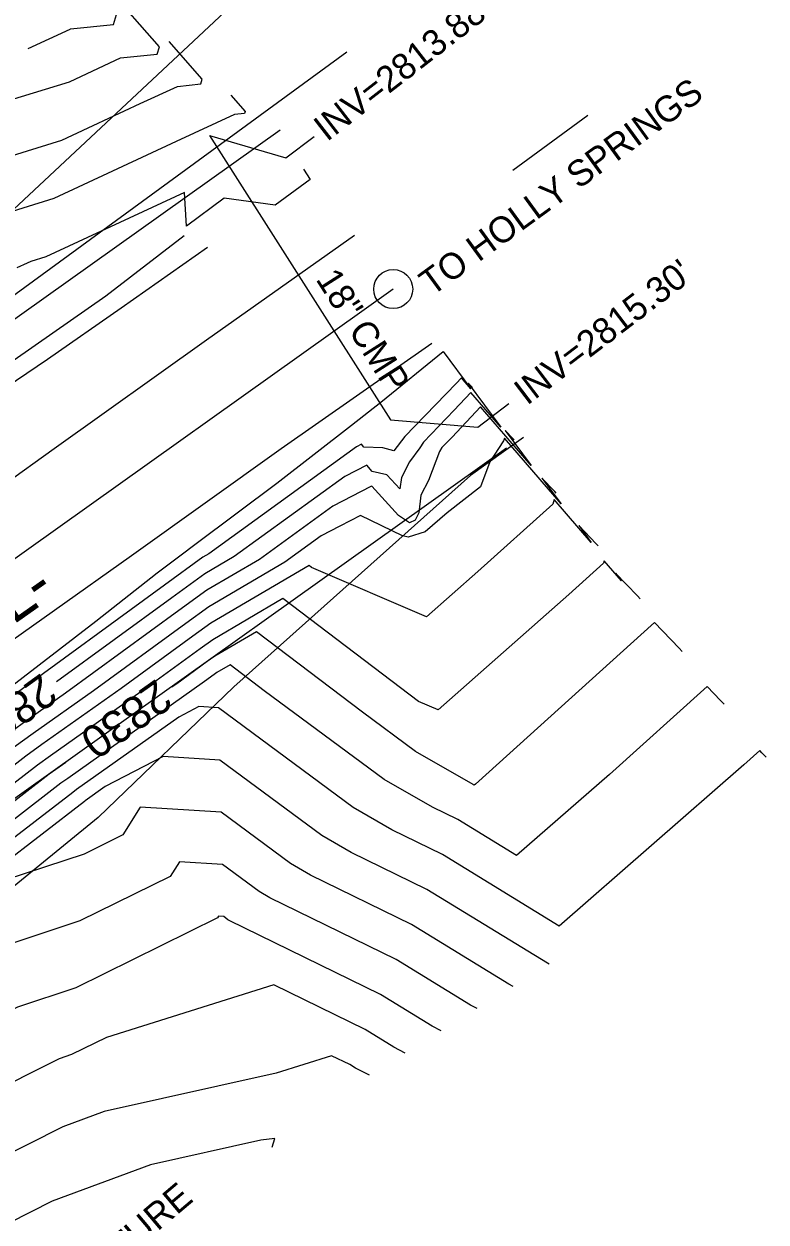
# Model space of a CAD drawing. Extents: x 1284446 to 1285480, y 969739 to 970628.
# Drawn here: x 1285132.8 to 1285246.9, y 970247.2 to 970431.3 of the extents above; entities that cross this region are included whole.
import ezdxf

# ---------------------------------------------------------------- set-up
doc = ezdxf.new("R2010")
doc.units = 0
for name, color, linetype in [('Default', 7, 'Continuous'), ('Exist Horizontal Alignment', 7, 'Continuous'), ('Exist Horizontal Alignment Direction Label', 7, 'Continuous'), ('Exist Horizontal Alignment Point', 7, 'Continuous'), ('Exist Other Culture Fence Line', 7, 'Continuous'), ('Exist Right of Way Line', 7, 'Continuous'), ('Exist Roads EOP', 7, 'Continuous'), ('Exist Roads EOP Leader', 7, 'Continuous'), ('Exist Roads EOP Text', 7, 'Continuous'), ('Exist Structure Minor Pipes CMP 18 Inch', 7, 'Continuous'), ('Exist Structure Minor Pipes CMP 18 Inch Invert', 7, 'Continuous'), ('Exist Structure Minor Pipes CMP 18 Inch Leader', 7, 'Continuous'), ('Exist Structure Minor Pipes CMP 18 Inch Text', 7, 'Continuous'), ('Exist Utilities Telephone UG Cable SUE LOS D', 7, 'Continuous'), ('Exist Vegetation Woods Line', 7, 'Continuous'), ('Exist Vegetation Woods Line Text', 7, 'Continuous')]:
    doc.layers.add(name, color=color, linetype=linetype)

msp = doc.modelspace()

# ---------------------------------------------------------------- linework, layer by layer
at = {"layer": 'Default'}
for points in [[(1285133.46, 970427.53), (1285139.92, 970430.53), (1285139.95, 970430.55), (1285146.57, 970431.23), (1285147.05, 970432.78), (1285136.21, 970445.15)], [(1285130.57, 970419.59), (1285139.8, 970422.45), (1285145.12, 970424.92), (1285147.64, 970426.09), (1285153.28, 970426.66), (1285153.64, 970427.8), (1285145.68, 970436.89)], [(1285123.4, 970408.76), (1285138.6, 970413.48), (1285150.67, 970419.08), (1285156.39, 970421.73), (1285160, 970422.1), (1285160.22, 970422.83), (1285155.14, 970428.62)], [(1285164.61, 970420.36), (1285166.8, 970417.86), (1285166.71, 970417.54), (1285165.15, 970417.38), (1285156.22, 970413.24), (1285137.39, 970404.5), (1285128.62, 970401.78)], [(1285175.75, 970408.99), (1285176.78, 970407.41), (1285171.4, 970403.49), (1285163.58, 970404.57), (1285157.79, 970400.22), (1285157.49, 970405.41), (1285136.18, 970395.53), (1285133.84, 970394.8), (1285133.27, 970394.54), (1285131.68, 970393.86)], [(1285129.56, 970328.54), (1285143.87, 970339.56), (1285153.29, 970346.97), (1285156.78, 970349.58), (1285159.25, 970351.48), (1285171.68, 970360.75), (1285183.17, 970369.64), (1285187.66, 970373.18), (1285197.23, 970380.98), (1285201.49, 970375.26), (1285200.06, 970376.91), (1285199.26, 970376.06), (1285191.37, 970367.94), (1285191.37, 970367.94), (1285191.34, 970367.9), (1285189.65, 970365.7)], [(1285201.73, 970375.46), (1285201.66, 970375.53), (1285201.08, 970376.13), (1285206.12, 970369.35), (1285201.52, 970374.69), (1285198.95, 970371.95), (1285194.21, 970367.07), (1285193.67, 970366.17), (1285192.08, 970364.04), (1285190.83, 970361.6), (1285190.6, 970359.86), (1285188.6, 970362.04), (1285186.34, 970362.55), (1285185.52, 970363.53), (1285182.11, 970361.76), (1285165.1, 970349.46), (1285160.61, 970346.82), (1285155.51, 970343.12), (1285137.8, 970330.22)], [(1285208.18, 970367.34), (1285208.03, 970367.5), (1285206.75, 970368.84), (1285210.75, 970363.45), (1285202.98, 970372.46), (1285198.63, 970367.84), (1285197.05, 970366.21), (1285196.69, 970365.6), (1285195.01, 970361.18), (1285193.83, 970358.89), (1285193.48, 970356.19), (1285192.92, 970355.06), (1285192.07, 970354.63), (1285190.38, 970355.79), (1285186.28, 970360.31), (1285186.1, 970360.21), (1285180.3, 970357.2), (1285169, 970349.03), (1285160.91, 970344.29), (1285156.6, 970341.16), (1285139.2, 970328.48), (1285132.88, 970324.02), (1285129.5, 970321.55)], [(1285214.63, 970359.23), (1285214.4, 970359.47), (1285212.41, 970361.54), (1285215.38, 970357.55), (1285206.66, 970367.66), (1285206.52, 970367.24), (1285204.43, 970364.05), (1285203, 970360.18), (1285197.87, 970356.19), (1285194.47, 970353.27), (1285191.86, 970352.47), (1285190.99, 970352.65), (1285184.54, 970355.77), (1285181.35, 970354.14), (1285178.48, 970352.65), (1285172.89, 970348.6), (1285161.22, 970341.76), (1285157.69, 970339.2), (1285143.47, 970328.84), (1285134.21, 970322.29), (1285131.3, 970320.16)], [(1285189.65, 970365.7), (1285187.95, 970366.16), (1285185.07, 970366.29), (1285184.71, 970366.72), (1285183.92, 970366.31), (1285161.21, 970349.88), (1285160.3, 970349.35), (1285154.41, 970345.08), (1285130.66, 970327.78)], [(1285221.08, 970351.11), (1285220.77, 970351.44), (1285218.08, 970354.24), (1285220.01, 970351.64), (1285214.33, 970358.23), (1285214.1, 970357.5), (1285202.55, 970347.16), (1285194.7, 970340.22), (1285177.02, 970347.78), (1285176.63, 970348.08), (1285161.52, 970339.22), (1285158.78, 970337.24), (1285147.74, 970329.19), (1285135.55, 970320.56), (1285133.1, 970318.78), (1285124.26, 970311.97)], [(1285227.53, 970342.99), (1285227.13, 970343.41), (1285223.75, 970346.94), (1285224.64, 970345.74), (1285222.01, 970348.79), (1285221.9, 970348.46), (1285216.54, 970343.66), (1285196.45, 970325.89), (1285193.43, 970327.18), (1285172.58, 970343), (1285161.82, 970336.69), (1285159.87, 970335.28), (1285152.01, 970329.55), (1285136.88, 970318.83), (1285134.9, 970317.39), (1285123.91, 970308.93)], [(1285233.98, 970334.88), (1285233.5, 970335.38), (1285229.74, 970339.31), (1285202.19, 970314.51), (1285202, 970314.34), (1285201.88, 970314.41), (1285201.83, 970314.44), (1285193, 970319.51), (1285184.84, 970325.55), (1285168.54, 970337.92), (1285162.13, 970334.16), (1285160.96, 970333.32), (1285156.28, 970329.9), (1285155.55, 970329.39)], [(1285240.43, 970326.76), (1285239.87, 970327.35), (1285237.82, 970329.49), (1285222.81, 970315.98), (1285208.53, 970303.51), (1285199.5, 970309.04), (1285195.58, 970310.96), (1285188.19, 970315.2), (1285169.75, 970328.85), (1285164.5, 970332.84), (1285162.43, 970331.63), (1285162.06, 970331.36), (1285160.55, 970330.25), (1285139.54, 970315.38), (1285138.49, 970314.62), (1285123.23, 970302.86)], [(1285246.88, 970318.65), (1285246.24, 970319.31), (1285245.9, 970319.67), (1285243.44, 970317.45), (1285215.07, 970292.68), (1285197.13, 970303.66), (1285189.33, 970307.48), (1285183.39, 970310.89), (1285162.68, 970326.22), (1285159.7, 970326.4), (1285156.63, 970324.81), (1285140.87, 970313.65), (1285140.29, 970313.23), (1285122.88, 970299.82), (1285117.15, 970295.78), (1285114.8, 970294.14), (1285096.39, 970280.52), (1285091.88, 970277.19), (1285085.84, 970272.96), (1285068.16, 970258.72), (1285065.65, 970256.96), (1285056.02, 970249.2), (1285050.07, 970245.13)], [(1285213.52, 970286.83), (1285213.26, 970286.96), (1285194.75, 970298.28), (1285183.09, 970303.99), (1285178.58, 970306.58), (1285162.89, 970318.2), (1285154.21, 970318.74), (1285145.3, 970314.12), (1285142.2, 970311.93), (1285142.09, 970311.84), (1285122.54, 970296.78), (1285119.11, 970294.37), (1285117.71, 970293.39), (1285097.04, 970278.11), (1285091.98, 970274.37), (1285088.22, 970271.73), (1285068.36, 970255.74), (1285066.82, 970254.66), (1285056, 970245.94)], [(1285139.23, 970317.83), (1285138.21, 970317.11), (1285136.69, 970316), (1285123.57, 970305.89), (1285113.21, 970298.6), (1285108.98, 970295.63), (1285095.08, 970285.36), (1285091.68, 970282.84), (1285081.08, 970275.41), (1285067.77, 970264.69), (1285063.31, 970261.56), (1285059.05, 970258.13)], [(1285207.99, 970283.41), (1285207.36, 970283.74), (1285192.38, 970292.91), (1285176.84, 970300.51), (1285173.77, 970302.28), (1285163.09, 970310.18), (1285150.65, 970310.95), (1285148.02, 970306.69), (1285142.04, 970303.74), (1285130.02, 970299.77), (1285122.2, 970293.75), (1285121.08, 970292.96), (1285120.63, 970292.64), (1285097.69, 970275.69), (1285092.08, 970271.54), (1285090.59, 970270.5), (1285068.56, 970252.76), (1285067.99, 970252.36), (1285055.98, 970242.68)], [(1285202.47, 970279.99), (1285201.46, 970280.52), (1285190, 970287.53), (1285170.6, 970297.03), (1285168.97, 970297.97), (1285163.3, 970302.16), (1285156.69, 970302.57), (1285155.29, 970300.31), (1285141.39, 970293.47), (1285125.36, 970288.17), (1285120.52, 970285.75), (1285114.1, 970281.28)], [(1285196.95, 970276.58), (1285195.55, 970277.3), (1285187.63, 970282.15), (1285164.35, 970293.55), (1285164.16, 970293.66), (1285163.5, 970294.15), (1285162.73, 970294.19), (1285162.57, 970293.93), (1285140.75, 970283.19), (1285131.79, 970280.24), (1285117.6, 970273.11), (1285105.88, 970264.97), (1285101.9, 970262.95), (1285098.82, 970260.79), (1285087.32, 970251.28), (1285076, 970241.31)], [(1285191.42, 970273.16), (1285189.65, 970274.08), (1285185.25, 970276.77), (1285171.22, 970283.64), (1285145.48, 970275.56), (1285140.11, 970272.92), (1285138.22, 970272.3), (1285114.68, 970260.48), (1285111.52, 970258.28), (1285104.66, 970254.8), (1285103.77, 970254.18), (1285100.48, 970251.46), (1285081.17, 970234.46)], [(1285185.9, 970269.75), (1285183.75, 970270.86), (1285182.88, 970271.4), (1285180.09, 970272.76), (1285171.59, 970270.09), (1285145.15, 970264.19), (1285138.76, 970261.82), (1285117.53, 970251.11), (1285116.87, 970250.85), (1285110.27, 970247.51), (1285106.27, 970244.77)], [(1285170.93, 970258.68), (1285171.39, 970260.03), (1285169.19, 970259.8), (1285152.25, 970256.01), (1285137.15, 970250.41), (1285123.76, 970243.66)]]:
    msp.add_lwpolyline(points, dxfattribs=at)
at = {"layer": 'Exist Horizontal Alignment'}
msp.add_line((1285189.56, 970390.57), (1284976.81, 970239.08), dxfattribs=at)
at = {"layer": 'Exist Horizontal Alignment Point'}
msp.add_circle((1285189.56, 970390.57), 3, dxfattribs=at)
at = {"layer": 'Exist Other Culture Fence Line'}
for points in [[(1285182.44, 970426.98), (1285127.53, 970386.93), (1285081.55, 970356.81), (1285037.11, 970332.56), (1285005.28, 970312.73), (1284979.02, 970288.01), (1284954.93, 970267.09)], [(1285209.58, 970367.74), (1285201.45, 970361.95), (1285165.07, 970329.44), (1285144.23, 970309.38)], [(1285144.23, 970309.38), (1285093.66, 970268.13), (1285055.96, 970240.9), (1285022.08, 970217.01), (1284994.2, 970199.4), (1284971, 970182.03), (1284973.25, 970175.79), (1284968.86, 970139.55), (1284964.87, 970125.31)]]:
    msp.add_lwpolyline(points, dxfattribs=at)
at = {"layer": 'Exist Right of Way Line'}
for p, q in [((1285172.16, 970415.01), (1284959.41, 970263.52)), ((1285206.96, 970366.13), (1284994.21, 970214.64))]:
    msp.add_line(p, q, dxfattribs=at)
at = {"layer": 'Exist Roads EOP'}
for points in [[(1284915.49, 970211.59), (1284915.7, 970211.69), (1284934.18, 970222.25), (1284952.29, 970234.31), (1284978.04, 970252.15), (1285001.96, 970268.99), (1285024.01, 970284.75), (1285046.43, 970300.94), (1285068.79, 970317), (1285091.5, 970333.21), (1285113.88, 970349.18), (1285137.46, 970366.05), (1285160.86, 970382.78), (1285183.61, 970398.87)], [(1284906.42, 970183.31), (1284909.89, 970185.39), (1284925.09, 970194), (1284944.45, 970205.72), (1284965.49, 970219.25), (1284989.1, 970235.63), (1285013.02, 970252.46), (1285035.6, 970268.52), (1285058.25, 970284.75), (1285080.34, 970300.38), (1285103.05, 970316.58), (1285125.6, 970332.83), (1285149.35, 970349.65), (1285172.35, 970366.09), (1285195.52, 970382.27)]]:
    msp.add_lwpolyline(points, dxfattribs=at)
at = {"layer": 'Exist Roads EOP Leader'}
msp.add_lwpolyline([(1285219.5, 970417.25), (1285207.94, 970408.81)], dxfattribs=at)
at = {"layer": 'Exist Structure Minor Pipes CMP 18 Inch'}
msp.add_line((1285161.32, 970414.17), (1285189.12, 970370.5), dxfattribs=at)
at = {"layer": 'Exist Structure Minor Pipes CMP 18 Inch Leader'}
for points in [[(1285161.32, 970414.17), (1285173.08, 970410.76), (1285177.43, 970414)], [(1285189.12, 970370.5), (1285202.56, 970369.35), (1285207.33, 970372.99)]]:
    msp.add_lwpolyline(points, dxfattribs=at)
at = {"layer": 'Exist Utilities Telephone UG Cable SUE LOS D'}
for points in [[(1284995.56, 970283.65), (1284999.52, 970284.32), (1285005.72, 970286.69), (1285022.35, 970297.73), (1285042.02, 970311.35), (1285061.21, 970326.65), (1285074.25, 970336.9), (1285086.97, 970346.55), (1285104.29, 970362.01), (1285123.12, 970374.03), (1285145.38, 970389.54), (1285157.44, 970398.83)], [(1284995.24, 970283.08), (1284999.73, 970282.13), (1285005, 970282.93), (1285013.35, 970288.3), (1285023.1, 970294.39), (1285031.08, 970299.64), (1285042.84, 970308.55), (1285053.73, 970317.61), (1285070.11, 970329.42), (1285082.83, 970339.22), (1285100.9, 970353.83), (1285117.45, 970367.01), (1285136.41, 970379.81), (1285147.73, 970387.67), (1285161, 970397.03)]]:
    msp.add_lwpolyline(points, dxfattribs=at)
at = {"layer": 'Exist Vegetation Woods Line'}
msp.add_lwpolyline([(1285171.52, 970440.57), (1285121.64, 970393.92), (1285081.63, 970356.87), (1285045.47, 970320.17), (1285013.5, 970297.41), (1284993.36, 970280.22), (1284932.55, 970245.36), (1284996.18, 970336), (1285054.45, 970386.33), (1285100.52, 970417.69), (1285131.32, 970449.81)], dxfattribs=at)

# ---------------------------------------------------------------- texts
at = {"layer": 'Default'}
for s, rotation, p in [('2820', 215.9393, (1285135.47, 970331.66)), ('2830', 215.3017, (1285153.19, 970330.78))]:
    msp.add_text(s, height=5, rotation=rotation, dxfattribs=at).set_placement(p)
at = {"layer": 'Exist Horizontal Alignment Direction Label'}
msp.add_text('-EL-', height=7, rotation=35.2154, dxfattribs=at).set_placement((1285123.45, 970333.49))
at = {"layer": 'Exist Roads EOP Text'}
msp.add_text('TO HOLLY SPRINGS', height=4, rotation=36.0792, dxfattribs=at).set_placement((1285195.49, 970389.39))
at = {"layer": 'Exist Structure Minor Pipes CMP 18 Inch Invert'}
for s, rotation, p in [("INV=2813.88'", 37.807, (1285179.37, 970413.14)), ("INV=2815.30'", 37.3169, (1285210.13, 970372.61))]:
    msp.add_text(s, height=4, rotation=rotation, dxfattribs=at).set_placement(p)
at = {"layer": 'Exist Structure Minor Pipes CMP 18 Inch Text'}
msp.add_text('18" CMP', height=4, rotation=302.4831, dxfattribs=at).set_placement((1285177.57, 970392.09))
at = {"layer": 'Exist Vegetation Woods Line Text'}
msp.add_text('PASTURE', height=4, rotation=40.2069, dxfattribs=at).set_placement((1285139.72, 970234.19))

doc.saveas('drawing.dxf')
